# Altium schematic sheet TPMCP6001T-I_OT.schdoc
size 127 x 101 mm
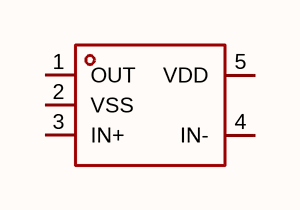
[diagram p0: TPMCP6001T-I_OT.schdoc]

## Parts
U?  tpmcp6001t-i/ot  [SOT-23-5_L2.9-W1.6-P0.95-LS2.8-BR]  (value not drawn)

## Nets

Not connected (* = marked no-connect by the designer): U? 1(OUT) 2(VSS) 3(IN+) 4(IN-) 5(VDD)

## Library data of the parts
U? = tpmcp6001t-i/ot: 放大器数:1;轨到轨:轨到轨输入,轨到轨输出;增益带宽积(GBW):1MHz;输入失调电压(Vos):5mV;压摆率(SR):1.06V/us;输入偏置电流(Ib):10pA;; Manufacturer: TECH PUBLIC(台舟); AddInBom: yes; ModelId: 7ba65df16e7b4570af156e925f9c37fe; ModelTransform: 114.173,114.173,0,90,0,0,0,0,0; Number of Channels: 1; Maximum Power Supply Range (Vdd-Vss): 7V; Gain Bandwidth Product: 1MHz; Vos - Input Offset Voltage: 5mV; Input Offset Voltage Drift(Vos TC): 2uV/℃; Ib - Input Bias Current: 10pA; Input Voltage Noise Density: 50nV/√Hz@10kHz; Common Mode Rejection Ratio(CMRR): 80dB; Quiescent Current: 55uA; Output Current: 20mA; Single supply: 1.8V~5.5V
